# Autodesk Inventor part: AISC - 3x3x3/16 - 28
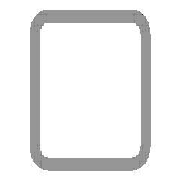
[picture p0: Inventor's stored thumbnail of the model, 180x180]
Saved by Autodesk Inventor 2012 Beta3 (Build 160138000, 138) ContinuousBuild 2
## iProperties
IsCustomPart: 1
Created: 2011-01
Part Number: AISC - 3x3x3/16 - 28
Material: Steel, Mild
Description: Tube
Document SubType Name: Modeling
Standard: ANSI
Designer: Beta-8540w
Standards Organization: ANSI
Language: en-US
Size Designation: 3x3x3/16
Categories: <MemberInstance><Categories><Category DisplayName="Structural Shapes" InternalName="089c4875-fa83-4c05-b084-43b9cc11f5ed" Mnemonic="GRDR"><CategoryParameter Dis
Stock Number: 3x3x3/16
Density: 7.86 g/cm^3
_CCFamilyMember: 9
_CCFamilyDisplayName: ANSI AISC (Square) - Tube
_FrameMemberDoc: Frame Member File
_Version: 15.0.0
_GetPNFromCC: 1
G_L: 28.000 in
G_W: 3.000 in
G_H: 3.000 in
Author: Beta-8540w
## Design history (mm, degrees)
node "Start plane"
node "End plane"
sketch "Sketch"
  geometry: L1 (-38.1, -28.575)-(-38.1, 28.575); L2 (-28.575, 38.1)-(28.575, 38.1); L3 (38.1, 28.575)-(38.1, -28.575); L4 (28.575, -38.1)-(-28.575, -38.1); L5 (-28.575, 33.337)-(28.575, 33.338); L6 (33.338, 28.575)-(33.338, -28.575); L7 (28.575, -33.337)-(-28.575, -33.338); L8 (-33.338, -28.575)-(-33.338, 28.575); L9 (0, 56.102)-(0, -56.102) reference; L10 (-56.102, 0)-(56.102, 0) reference; A1 r 9.525 centre (-28.575, -28.575) between (-38.1, -28.575) and (-28.575, -38.1); A2 r 9.525 centre (-28.575, 28.575) between (-28.575, 38.1) and (-38.1, 28.575); A3 r 9.525 centre (28.575, 28.575) between (38.1, 28.575) and (28.575, 38.1); A4 r 9.525 centre (28.575, -28.575) between (28.575, -38.1) and (38.1, -28.575); A5 r 4.763 centre (-28.575, 28.575) between (-28.575, 33.337) and (-33.338, 28.575); A6 r 4.763 centre (28.575, 28.575) between (33.338, 28.575) and (28.575, 33.338); A7 r 4.763 centre (28.575, -28.575) between (28.575, -33.337) and (33.338, -28.575); A8 r 4.763 centre (-28.575, -28.575) between (-33.338, -28.575) and (-28.575, -33.338)
  constraints: 16 end point, 16 point on circle, 8 centre point, 8 tangent, 4 parallel, 3 equal radius, 2 perpendicular, 7 other
  dimensions: "d10" = 76.2 distance between parallel lines of L2 L4 (= G_H); "d11" = 76.2 distance between parallel lines of L1 L3 (= G_W); "d12" = 4.7625 distance between parallel lines of L3 L6 (= G_T); "d15" = 38.1 distance between parallel lines of L2 L10 (= 0.5 x d10); "d16" = 38.1 distance between parallel lines of L9 L3 (= 0.5 x d11); "d17" = 9.525 radius of A1 (= G_IR)
extrude "Body" new body sketch "Sketch" stored distance "d3" = 711.2 (= G_L); taper "d4" = 0 deg
node "Driven Length"
  sketch "Sketch3"
    geometry: L1 (0, 0)-(10, 0) reference
    constraints: 2 end point, 1 horizontal
  workplane "Work Plane3"
  sketch "Sketch4"
    geometry: L1 (-2, 0)-(12, 0) reference; L2 (-2, 711.2)-(12, 711.2) reference
    dimensions: "d19" = 711.2 distance between parallel lines of L1 L2 (derived)
body "Solid1"
other parameters: "G_W" = 76.2 [user parameter; used in 1 equation term], "G_H" = 76.2 [user parameter; used in 1 equation term], "G_T" = 4.7625 [user parameter; used in 1 equation term], "G_IR" = 9.525 [user parameter; used in 1 equation term], "G_L" = 711.2 (= d19) [user parameter; used in 1 equation term], "G_OFFSET_START" = 0 [user parameter; used in 1 equation term], "G_OFFSET_END" = 0 [user parameter; used in 1 equation term], "d13" = 0 (computed from G_OFFSET_START), "d14" = 711.2 (= G_OFFSET_END + B_L), "B_L" = 711.2 [user parameter; used in 1 equation term], "d18" = 90 deg
